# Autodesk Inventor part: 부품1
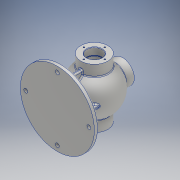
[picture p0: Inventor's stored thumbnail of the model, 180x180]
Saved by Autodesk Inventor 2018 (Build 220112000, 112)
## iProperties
Created: 2020-08
Part Number: 부품1
Material: 알루미늄 6061
Document SubType Name: Modeling
Designer: Administrator
Density: 2.7 g/cm^3
Appearance: 알루미늄 - 평지
Mass: 1752.15 g
Surface Area: 1344.79 cm^2
Volume: 648.944 cm^3
Author: Administrator
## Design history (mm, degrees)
sketch "스케치1"
  geometry: L1 (-85, 0)-(-85, 85); L2 (-85, 85)-(-75, 85); L3 (-75, 85)-(-75, 0); L4 (-75, 0)-(-85, 0); L5 (53, 0)-(-53, 0); A1 r 53 centre (0, 0) between (53, 0) and (-53, 0); 1 further point
  constraints: 10 end point, 2 horizontal, 2 point on circle, 1 centre point, 1 coincident, 1 perpendicular, 1 vertical
  dimensions: "d2" = 85 distance of L1.start L1.end; "d3" = 10 distance of L1.end L2.end
revolve "회전1" sketch "스케치1" stored, may be unused: angle "d4" = 90 deg
sketch "스케치2"
  geometry: L1 (0, 68)-(31, 68); L2 (31, 68)-(31, -68); L3 (31, -68)-(0, -68); L4 (0, 68)-(0, -68); 1 further point
  constraints: 8 end point, 2 perpendicular, 1 vertical
revolve "회전2" sketch "스케치2" stored, may be unused: angle "d9" = 90 deg
sketch "스케치3"
  geometry: L1 (85, -75)-(-85, -75) reference; L2 (43, -75)-(-43, -75); L3 (-43, -75)-(-43, 0); L4 (-43, 0)-(43, 0); L5 (43, 0)-(43, -75); 1 further point
  constraints: 8 end point, 3 perpendicular, 1 point on line
extrude "돌출1" join sketch "스케치3" stored distance "d12" = 8; taper "d13" = 0 deg
sketch "스케치4"
  geometry: L1 (-75, -85)-(-75, 85) reference; L2 (-75, -43.012)-(-75, 43); L3 (-75, 43)-(3.544, 42.988); L4 (-31, 42.988)-(31, 42.988) reference; L5 (3.544, 42.988)-(3.544, -43.012); L6 (3.544, -43.012)-(-75, -43.012); A1 r 4.279 centre (3.544, 38.71) between (3.543, 34.431) and (3.544, 42.988); A2 r 4.279 centre (3.544, 38.71) between (3.544, 42.988) and (3.543, 34.431); 1 further point
  constraints: 8 end point, 4 point on circle, 3 point on line, 3 tangent, 2 centre point, 2 perpendicular
extrude "돌출2" join sketch "스케치4" stored distance "d17" = 8; taper "d18" = 0 deg
sketch "스케치5"
  geometry: L1 (43, 0)-(-43, 0); A1 r 43 centre (0, 0) between (43, 0) and (-43, 0); 1 further point
  constraints: 2 end point, 2 point on circle, 1 centre point, 1 coincident, 1 horizontal
revolve "회전3" sketch "스케치5" stored, may be unused: angle "d20" = 90 deg
sketch "스케치6"
  geometry: L1 (0, 74.444)-(17.5, 74.444); L2 (17.5, 74.444)-(17.5, -78.998); L3 (17.5, -78.998)-(0, -78.998); L4 (0, 74.444)-(0, -78.998); 1 further point
  constraints: 8 end point, 1 perpendicular, 1 vertical
revolve "회전4" sketch "스케치6" stored, may be unused: angle "d23" = 90 deg
sketch "스케치7"
  geometry: L1 (0, 52)-(18.5, 52); L2 (18.5, 52)-(18.5, 50.25); L3 (18.5, 50.25)-(0, 50.25); L4 (0, 50.25)-(0, 52); L5 (0, -52)-(18.5, -52); L6 (18.5, -52)-(18.5, -50.25); L7 (18.5, -50.25)-(0, -50.25); L8 (0, -50.25)-(0, -52); 1 further point
  constraints: 16 end point, 2 perpendicular, 1 horizontal
revolve "회전5" sketch "스케치7" stored, may be unused: angle "d27" = 90 deg
node "작업 평면1"
sketch "스케치8"
  geometry: C1 r 27 at (0, 0); 1 further point
  constraints: 1 centre point, 1 coincident
  dimensions: "d28" = 54 diameter of C1
extrude "돌출3" join sketch "스케치8" stored distance "d29" = 80; taper "d30" = 0 deg
sketch "스케치9"
  geometry: L1 (0, 65)-(-39.777, 65); L2 (-39.777, 65)-(-39.777, 103.189); L3 (-39.777, 103.189)-(41.506, 103.189); L4 (41.506, 103.189)-(41.506, 65); L5 (41.506, 65)-(0, 65); 1 further point
  constraints: 10 end point, 4 perpendicular, 1 horizontal, 1 point on line
  dimensions: "d32" = 81.28308 distance between parallel lines of L2 L4; "d33" = 38.18916 distance between parallel lines of L5 L3; "d34" = 41.50625 distance from line of point (0, 0) L4; "d35" = 65 distance from line of point (0, 0) L5; "d36" = 41.50625 distance from line of L1.start L4
extrude "돌출4" cut sketch "스케치9" distance "d37" = 100; taper "d38" = 0 deg
sketch "스케치10"
  geometry: C1 r 13 at (0, 0); 1 further point
  constraints: 1 centre point, 1 coincident
  dimensions: "d39" = 26 diameter of C1
extrude "돌출5" cut sketch "스케치10" distance "d40" = 50; taper "d41" = 0 deg
sketch "스케치11"
  geometry: C1 r 2 at (-20, 0); 1 further point
  constraints: 1 centre point
  dimensions: "d43" = 4 diameter of C1
hole "구멍1" sketch "스케치11" at (-20, 0) diameter "d44" = 3.242; stored, may be unused: countersink angle "d48" = 90 deg, drill point angle "d50" = 118 deg; dims "d45" = 12, "d46" = 4, "d47" = 2, "d49" = 15
sketch "스케치12"
  geometry: L1 (43, 0)-(-43, 0); A1 r 43 centre (0, 0) between (43, 0) and (-43, 0); 1 further point
  constraints: 2 end point, 2 point on circle, 1 centre point, 1 coincident, 1 horizontal
revolve "회전6" sketch "스케치12" stored, may be unused: angle "d54" = 350 deg
sketch "스케치13"
  geometry: C1 r 4.5 at (-72.5, 0); 2 further points
  constraints: 1 centre point
  dimensions: "d56" = 9 diameter of C1
extrude "돌출6" cut sketch "스케치13" distance "d57" = 50; taper "d58" = 0 deg
sketch "스케치14"
  geometry: L1 (-75, 4)-(-75, -4) reference; L2 (-75, -52)-(-75, 52); L3 (-75, 52)-(-25.941, 52); L4 (-25.941, 52)-(-25.941, -52); L5 (-25.941, -52)-(-75, -52); 1 further point
  constraints: 8 end point, 2 perpendicular, 1 collinear, 1 horizontal
  dimensions: "d63" = 104 distance of L3.end L4.end
extrude "돌출7" join sketch "스케치14" stored distance "d64" = 8; taper "d65" = 0 deg
sketch "스케치15"
  geometry: L1 (43, 0)-(-43, 0); A1 r 43 centre (0, 0) between (43, 0) and (-43, 0); 1 further point
  constraints: 2 end point, 2 point on circle, 1 centre point, 1 coincident, 1 horizontal
revolve "회전7" sketch "스케치15" stored, may be unused: angle "d66" = 350 deg
fillet "모깎기1" dims "d67" = 3
fillet "모깎기2" dims "d68" = 3
chamfer "모따기1" distance "d69" = 1; stored, may be unused: second distance "d70" = 2, angle "d71" = 45 deg
sketch "스케치16"
  geometry: C1 r 2 at (0, 24); 1 further point
  constraints: 1 centre point
  dimensions: "d73" = 4 diameter of C1
hole "구멍2" sketch "스케치16" at (0, 24) diameter "d75" = 3.242; stored, may be unused: countersink angle "d79" = 90 deg, drill point angle "d81" = 118 deg; dims "d76" = 12, "d77" = 4, "d78" = 2, "d80" = 15
node "작업 평면2"
node "작업 평면3"
sketch "스케치17"
  geometry: L1 (-12, -27)-(-12, 27) reference; L2 (-12, -27)-(-12, 0); L3 (-12, 0)-(-3, 0); 2 further points
  constraints: 4 end point, 1 coincident, 1 midpoint, 1 perpendicular, 1 other
  dimensions: "d85" = 27 distance of L1.start L2.end (derived); "d86" = 9 distance of L2.end L3.end
feature "엠보싱1" sketch "스케치17" dims "d13" = 0, "d87" = 0.5, "d88" = 0
node "솔리드1"
pattern_circular "원형 패턴1" dims angle "d52" = 360 deg
pattern_circular "원형 패턴2" dims angle "d60" = 360 deg
pattern_circular "원형 패턴3" dims angle "d83" = 360 deg
mirror "미러1"
